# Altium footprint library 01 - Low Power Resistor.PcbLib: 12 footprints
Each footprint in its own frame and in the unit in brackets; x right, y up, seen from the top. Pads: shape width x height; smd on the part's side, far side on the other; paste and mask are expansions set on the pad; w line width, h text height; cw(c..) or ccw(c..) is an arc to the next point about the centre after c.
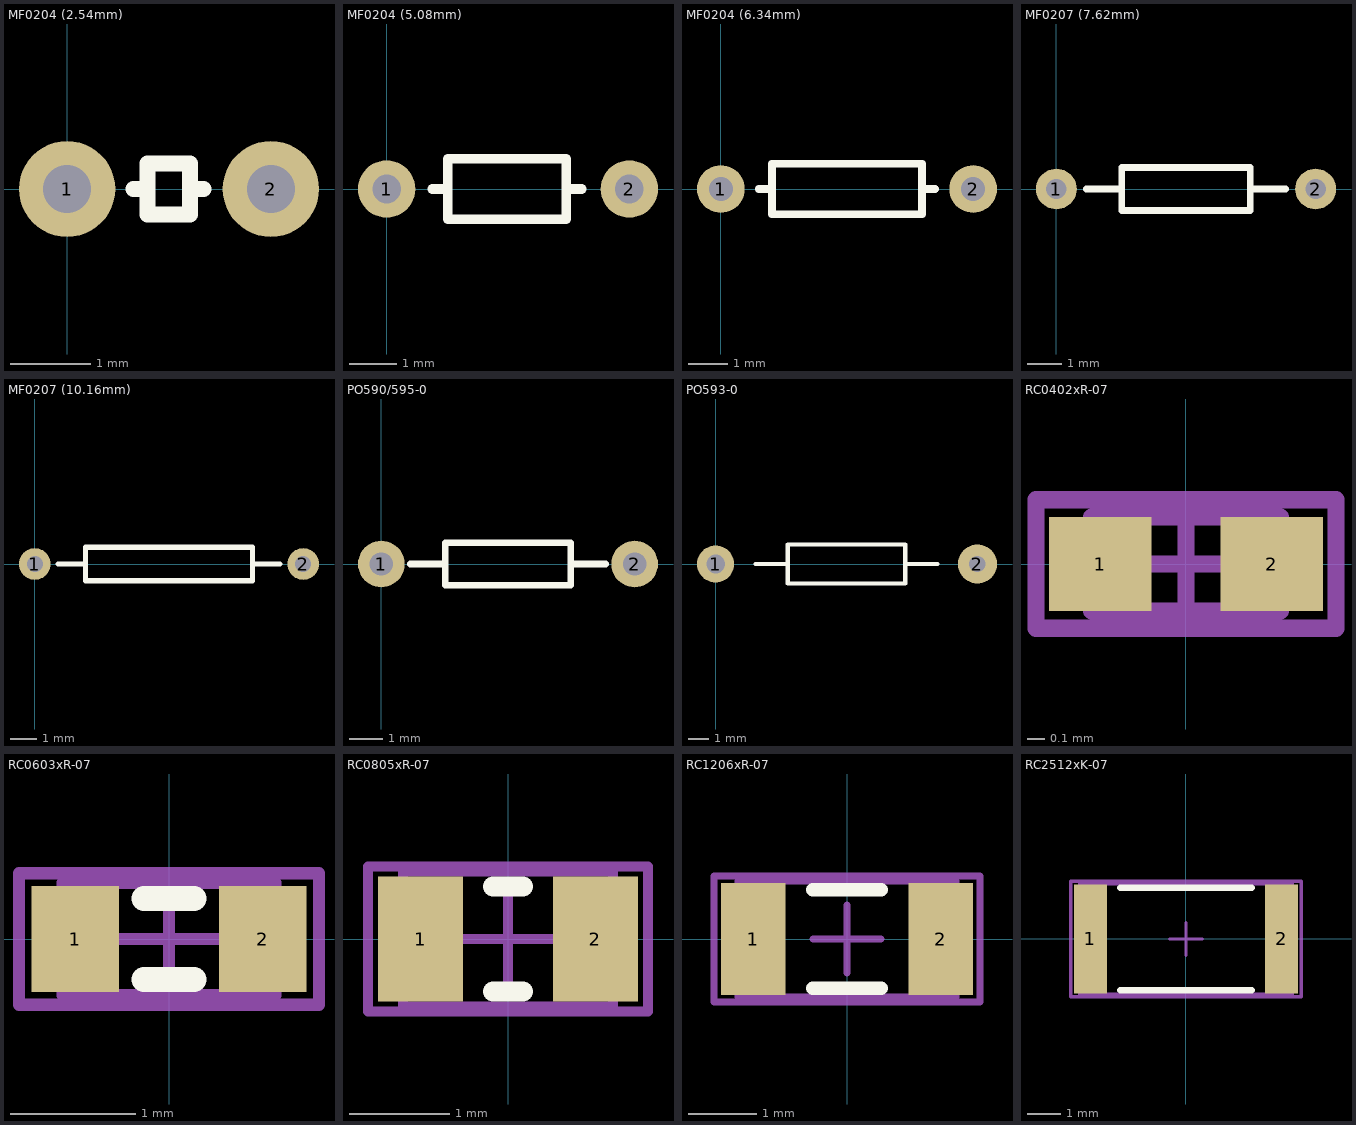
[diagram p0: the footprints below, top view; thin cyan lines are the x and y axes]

## MF0204 (2.54mm) [mm] "Axial - 2.54mm, Body: 3.6mm x 5mm"
height 5
pads (2):
  round 1.2 hole 0.6: 1(0,0) 2(2.54,0)
Top Overlay:
  lines w0.2: 0.826,0 0.991,0 ; 1.537,0 1.702,0 ; 1.001,-0.318 1.001,0.318 1.534,0.318 1.534,-0.318 1.001,-0.318
3D body: height 7.25, standoff -1.5, extent -0.922,-0.92 2.79,0.92

## MF0204 (5.08mm) [mm] "Axial - 5.08mm, Body: 3.6mm x 1.8mm"
height 1.8
pads (2):
  round 1.2 hole 0.6: 1(0,0) 2(5.08,0)
Top Overlay:
  lines w0.2: 0.953,0 1.28,0 ; 3.76,0 4.088,0 ; 1.28,-0.635 1.28,0.635 3.76,0.635 3.76,-0.635 1.28,-0.635

## MF0204 (6.34mm) [mm] "Axial - 6.34mm, Body: 3.6mm x 1.8mm"
height 1.8
pads (2):
  round 1.2 hole 0.6: 1(0,0) 2(6.34,0)
Top Overlay:
  lines w0.2: 0.953,0 1.28,0 ; 5.05,0 5.378,0 ; 1.28,-0.635 5.05,-0.635 5.05,0.635 1.28,0.635 1.28,-0.635
3D body: height 2.42, standoff -1.5, extent -0.254,-0.92 6.604,0.92

## MF0207 (7.62mm) [mm] "Axial - 7.62mm, Body: 6.3mm x 2.4mm"
height 2.4
pads (2):
  round 1.2 hole 0.6: 1(0,0) 2(7.62,0)
Top Overlay:
  lines w0.2: 0.875,0 1.92,0 ; 5.7,0 6.745,0 ; 1.92,-0.635 5.7,-0.635 5.7,0.635 1.92,0.635 1.92,-0.635
3D body: height 2.5, standoff -1.5, extent -0.229,-1 7.871,1

## MF0207 (10.16mm) [mm] "Axial - 10.16mm, Body: 6.3mm x 2.4mm"
height 2.4
pads (2):
  round 1.2 hole 0.6: 1(0,0) 2(10.16,0)
Top Overlay:
  lines w0.2: 0.875,0 1.92,0 ; 8.24,0 9.285,0 ; 1.92,-0.635 1.92,0.635 8.24,0.635 8.24,-0.635 1.92,-0.635
3D body: height 4.12, standoff -1.06, extent -0.279,-1.118 10.439,1.118

## PO590/595-0 [mm] "Axial - 7.62mm, Body: 6.7mm x 2.5mm"
height 2.5
pads (2):
  round 1.4 hole 0.7: 1(0,0) 2(7.62,0)
Top Overlay:
  lines w0.2: 0.875,0 1.92,0 ; 5.7,0 6.745,0 ; 1.92,-0.635 5.7,-0.635 5.7,0.635 1.92,0.635 1.92,-0.635

## PO593-0 [mm] "Axial - 12.7mm, Body: 12.0 mm x 4.1mm"
height 4.1
pads (2):
  round 1.8 hole 0.9: 1(0,0)
  round 1.9 hole 0.8: 2(12.7,0)
Top Overlay:
  lines w0.2: 1.933,0 3.501,0 ; 9.2,0 10.768,0 ; 3.501,-0.952 9.2,-0.952 9.2,0.952 3.501,0.952 3.501,-0.952

## RC0402xR-07 [mm] "Chip Resistor, 2-Leads, Body 1,0x0,5mm, IPC High Density"
height 0.4
pads (2):
  rect 0.6x0.55 smd: 1(-0.5,0) 2(0.5,0)
Mechanical 13:
  lines w0.1: -0.55,-0.275 -0.55,0.275 0.55,0.275 0.55,-0.275 -0.55,-0.275
Mechanical 15:
  lines w0.1: -0.275,0 0.275,0 ; 0,-0.275 0,0.275 ; -0.875,-0.375 -0.875,0.375 0.875,0.375 0.875,-0.375 -0.875,-0.375
3D body: height 0.2, standoff 0, extent -0.492,-0.3 0.508,0.3

## RC0603xR-07 [mm] "Chip Resistor, 2-Leads, Body 1,6x0,8mm, IPC High Density"
height 0.55
pads (2):
  rect 0.7x0.85 smd: 1(-0.75,0) 2(0.75,0)
Top Overlay:
  lines w0.2: -0.2,-0.325 0.2,-0.325 ; -0.2,0.325 0.2,0.325
Mechanical 13:
  lines w0.1: -0.85,-0.45 0.85,-0.45 0.85,0.45 -0.85,0.45 -0.85,-0.45
Mechanical 15:
  lines w0.1: -0.45,0 0.45,0 ; 0,-0.45 0,0.45 ; -1.2,-0.525 1.2,-0.525 1.2,0.525 -1.2,0.525 -1.2,-0.525
3D body: height 0.3, standoff 0, extent -0.813,-0.4 0.787,0.4

## RC0805xR-07 [mm] "Chip Resistor, 2-Leads, Body 2,0x1,3mm, IPC High Density"
height 0.6
pads (2):
  rect 0.85x1.25 smd: 1(-0.875,0) 2(0.875,0)
Top Overlay:
  lines w0.2: -0.15,-0.525 0.15,-0.525 ; -0.15,0.525 0.15,0.525
Mechanical 13:
  lines w0.1: -1.05,-0.675 -1.05,0.675 1.05,0.675 1.05,-0.675 -1.05,-0.675
Mechanical 15:
  lines w0.1: -0.5,0 0.5,0 ; 0,-0.5 0,0.5 ; -1.4,-0.725 -1.4,0.725 1.4,0.725 1.4,-0.725 -1.4,-0.725
3D body: height 0.78, standoff 0, extent -0.984,-0.625 1.016,0.625

## RC1206xR-07 [mm] "Chip Resistor, 2-Leads, Body 3,1x1,6mm, IPC High Density"
height 0.65
pads (2):
  rect 0.95x1.65 smd: 1(-1.375,0) 2(1.375,0)
Top Overlay:
  lines w0.2: -0.5,-0.725 0.5,-0.725 ; -0.5,0.725 0.5,0.725
Mechanical 13:
  lines w0.1: -1.6,-0.85 -1.6,0.85 1.6,0.85 1.6,-0.85 -1.6,-0.85
Mechanical 15:
  lines w0.1: -0.5,0 0.5,0 ; 0,-0.5 0,0.5 ; -1.95,-0.925 -1.95,0.925 1.95,0.925 1.95,-0.925 -1.95,-0.925
3D body: height 1, standoff 0, extent -1.6,-0.787 1.6,0.813

## RC2512xK-07 [mm] "Chip Resistor, 2-Leads, Body 6,3x3,2mm, IPC High Density"
height 0.65
pads (2):
  rect 1x3.3 smd: 1(-2.9,0) 2(2.9,0)
Top Overlay:
  lines w0.2: -2,-1.55 2,-1.55 ; -2,1.55 2,1.55
Mechanical 13:
  lines w0.1: -3.225,-1.675 -3.225,1.675 3.225,1.675 3.225,-1.675 -3.225,-1.675
Mechanical 15:
  lines w0.1: -0.5,0 0.5,0 ; 0,-0.5 0,0.5 ; -3.5,-1.75 -3.5,1.75 3.5,1.75 3.5,-1.75 -3.5,-1.75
